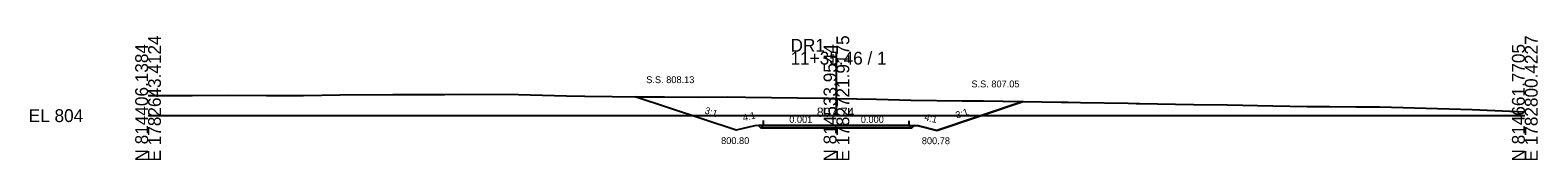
# Model space of a CAD drawing. Extents: x -26 to 303, y -10 to 2017.
# Drawn here: x -25.7 to 302.8, y 1990.3 to 2017.4 of the extents above; entities that cross this region are included whole.
import ezdxf

# ---------------------------------------------------------------- set-up
doc = ezdxf.new("R2010")
doc.units = 0
for name, color, linetype in [('Exist Cross Section Cell', 7, 'Continuous'), ('Exist XS Center Line Elevation Label', 7, 'Continuous'), ('Exist XS Ground Line', 7, 'Continuous'), ('Prop XS Ditch Slope Text', 7, 'Continuous'), ('Prop XS Ditch Standard Text', 7, 'Continuous'), ('Prop XS Dump Level', 7, 'Continuous'), ('Prop XS Earthwork Shape', 7, 'Continuous'), ('Prop XS EOT Tick Mark', 7, 'Continuous'), ('Prop XS Finish Grade', 7, 'Continuous'), ('Prop XS Finish Grade Earthwork', 7, 'Continuous'), ('Prop XS Finish Grade Pavement', 7, 'Continuous'), ('Prop XS Pvmt Edge Slope', 7, 'Continuous'), ('Prop XS SE Text', 7, 'Continuous'), ('Prop XS Side Slope Text', 7, 'Continuous'), ('Prop XS SS Elevation Text', 7, 'Continuous'), ('Prop XS Subgrade Earthwork', 7, 'Continuous')]:
    doc.layers.add(name, color=color, linetype=linetype)

msp = doc.modelspace()

# ---------------------------------------------------------------- linework, layer by layer
at = {"layer": 'Exist Cross Section Cell'}
for p, q in [((150, 2000), (150, 2013.92)), ((0, 2000), (150, 2000)), ((150, 2000), (300, 2000))]:
    msp.add_line(p, q, dxfattribs=at)
at = {"layer": 'Exist XS Ground Line'}
for p, q in [((0, 2004.42), (3.43, 2004.41)), ((3.43, 2004.41), (9.59, 2004.42)), ((9.59, 2004.42), (17.62, 2004.47)), ((17.62, 2004.47), (25.82, 2004.41)), ((25.82, 2004.41), (29.15, 2004.4)), ((29.15, 2004.4), (33.87, 2004.4)), ((33.87, 2004.4), (41.78, 2004.51)), ((41.78, 2004.51), (53.33, 2004.61)), ((53.33, 2004.61), (61.51, 2004.61)), ((61.51, 2004.61), (64.63, 2004.6)), ((64.63, 2004.6), (68.41, 2004.64)), ((68.41, 2004.64), (80.69, 2004.58)), ((80.69, 2004.58), (91.19, 2004.3)), ((91.19, 2004.3), (95.16, 2004.23)), ((95.16, 2004.23), (107.14, 2004.12)), ((107.14, 2004.12), (112.51, 2004.08)), ((112.51, 2004.08), (119.85, 2004.05)), ((119.85, 2004.05), (126.37, 2004.06)), ((126.37, 2004.06), (130.19, 2004.03)), ((130.19, 2004.03), (147.17, 2003.78)), ((147.17, 2003.78), (148.2, 2003.77)), ((148.2, 2003.77), (148.52, 2003.76)), ((148.52, 2003.76), (150, 2003.74)), ((150, 2003.74), (158.75, 2003.6)), ((158.75, 2003.6), (166.29, 2003.39)), ((166.29, 2003.39), (177.42, 2003.23)), ((177.42, 2003.23), (182.07, 2003.19)), ((182.07, 2003.19), (199, 2002.92)), ((199, 2002.92), (200.02, 2002.91)), ((200.02, 2002.91), (200.46, 2002.9)), ((200.46, 2002.9), (203.17, 2002.85)), ((203.17, 2002.85), (213.59, 2002.68)), ((213.59, 2002.68), (215.29, 2002.64)), ((215.29, 2002.64), (216.06, 2002.63)), ((216.06, 2002.63), (227.84, 2002.45)), ((227.84, 2002.45), (235.12, 2002.34)), ((235.12, 2002.34), (245.11, 2002.13)), ((245.11, 2002.13), (252.6, 2002)), ((252.6, 2002), (257.43, 2002)), ((257.43, 2002), (263.15, 2001.95)), ((263.15, 2001.95), (268.32, 2001.89)), ((268.32, 2001.89), (270.95, 2001.82)), ((270.95, 2001.82), (288.51, 2001.32)), ((288.51, 2001.32), (300, 2000.8))]:
    msp.add_line(p, q, dxfattribs=at)
at = {"layer": 'Prop XS Dump Level'}
for p, q in [((134.14, 1997.92), (150, 1997.91)), ((150, 1997.91), (165.86, 1997.9))]:
    msp.add_line(p, q, dxfattribs=at)
at = {"layer": 'Prop XS Earthwork Shape'}
msp.add_lwpolyline([(132.14, 1997.8), (128.14, 1996.8), (106.14, 2004.13), (107.14, 2004.12), (112.51, 2004.08), (119.85, 2004.05), (126.37, 2004.06), (130.19, 2004.03), (147.17, 2003.78), (148.2, 2003.77), (148.52, 2003.76), (150, 2003.74), (158.75, 2003.6), (166.29, 2003.39), (177.42, 2003.23), (182.07, 2003.19), (190.69, 2003.05), (171.86, 1996.78), (167.86, 1997.78), (166.96, 1997.83), (166.45, 1997.32), (150, 1997.32), (133.55, 1997.33), (133.04, 1997.85)], close=True, dxfattribs=at)
at = {"layer": 'Prop XS EOT Tick Mark'}
for p, q in [((134.14, 1997.92), (134.14, 1998.92)), ((165.86, 1997.9), (165.86, 1998.9))]:
    msp.add_line(p, q, dxfattribs=at)
at = {"layer": 'Prop XS Finish Grade'}
for p, q in [((134.14, 1997.92), (133.04, 1997.85)), ((165.86, 1997.9), (166.96, 1997.83))]:
    msp.add_line(p, q, dxfattribs=at)
at = {"layer": 'Prop XS Finish Grade Earthwork'}
for p, q in [((128.14, 1996.8), (106.14, 2004.13)), ((171.86, 1996.78), (190.69, 2003.05)), ((132.14, 1997.8), (128.14, 1996.8)), ((133.04, 1997.85), (132.14, 1997.8)), ((166.96, 1997.83), (167.86, 1997.78)), ((167.86, 1997.78), (171.86, 1996.78))]:
    msp.add_line(p, q, dxfattribs=at)
at = {"layer": 'Prop XS Finish Grade Pavement'}
for p, q in [((134.14, 1997.92), (150, 1997.91)), ((150, 1997.91), (165.86, 1997.9))]:
    msp.add_line(p, q, dxfattribs=at)
at = {"layer": 'Prop XS Pvmt Edge Slope'}
for p, q in [((134.14, 1997.92), (133.55, 1997.33)), ((165.86, 1997.9), (166.45, 1997.32))]:
    msp.add_line(p, q, dxfattribs=at)
at = {"layer": 'Prop XS Subgrade Earthwork'}
for p, q in [((133.55, 1997.33), (133.04, 1997.85)), ((166.45, 1997.32), (166.96, 1997.83)), ((133.55, 1997.33), (150, 1997.32)), ((150, 1997.32), (166.45, 1997.32))]:
    msp.add_line(p, q, dxfattribs=at)

# ---------------------------------------------------------------- texts
at = {"layer": 'Exist Cross Section Cell'}
for s, p in [('E 1782643.4124', (2.8, 1990)), ('E 1782721.9175', (152.8, 1990)), ('E 1782800.4227', (302.8, 1990)), ('N 814406.1384', (0, 1990)), ('N 814533.9544', (150, 1990)), ('N 814661.7705', (300, 1990))]:
    msp.add_text(s, height=2.8, rotation=90, dxfattribs=at).set_placement(p)
for s, p in [('11+35.46 / 1', (140, 2011.12)), ('DR1', (140, 2013.92)), ('EL 804', (-26, 1998.6))]:
    msp.add_text(s, height=2.8, dxfattribs=at).set_placement(p)
at = {"layer": 'Exist XS Center Line Elevation Label'}
msp.add_text('807.74', height=2, dxfattribs=at).set_placement((145.72, 1999.74))
at = {"layer": 'Prop XS Ditch Slope Text'}
for rotation, p in [(14.0362, (129.77, 1998.75)), (345.9638, (169.05, 1999.03))]:
    msp.add_text('4:1', height=1.5, rotation=rotation, dxfattribs=at).set_placement(p)
at = {"layer": 'Prop XS Ditch Standard Text'}
for s, p in [('800.80', (124.87, 1993.8)), ('800.78', (168.6, 1993.78))]:
    msp.add_text(s, height=1.5, dxfattribs=at).set_placement(p)
at = {"layer": 'Prop XS Dump Level'}
for p in [(132.14, 1997.76), (167.86, 1997.74)]:
    msp.add_text('Case1', height=0.04, dxfattribs=at).set_placement(p)
at = {"layer": 'Prop XS SE Text'}
for s, p in [('0.001', (139.72, 1998.41)), ('0.000', (155.31, 1998.41))]:
    msp.add_text(s, height=1.5, rotation=359.9714, dxfattribs=at).set_placement(p)
at = {"layer": 'Prop XS Side Slope Text'}
for rotation, p in [(341.5651, (121.15, 2000.52)), (18.4349, (176.26, 1999.34))]:
    msp.add_text('3:1', height=1.5, rotation=rotation, dxfattribs=at).set_placement(p)
at = {"layer": 'Prop XS SS Elevation Text'}
for s, p in [('S.S. 808.13', (108.56, 2007.08)), ('S.S. 807.05', (179.41, 2006.15))]:
    msp.add_text(s, height=1.5, dxfattribs=at).set_placement(p)

doc.saveas('drawing.dxf')
